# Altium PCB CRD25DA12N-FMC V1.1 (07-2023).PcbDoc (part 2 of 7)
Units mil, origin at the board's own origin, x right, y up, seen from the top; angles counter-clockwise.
Board outline 8000 x 8000 mil, 6 copper layers (Top Layer, Layer 2, Layer 3, Layer 4, Layer 5, Bottom Layer), stack 91 mil thick; 542 components, 315 nets, 1585 pads, 558 vias.
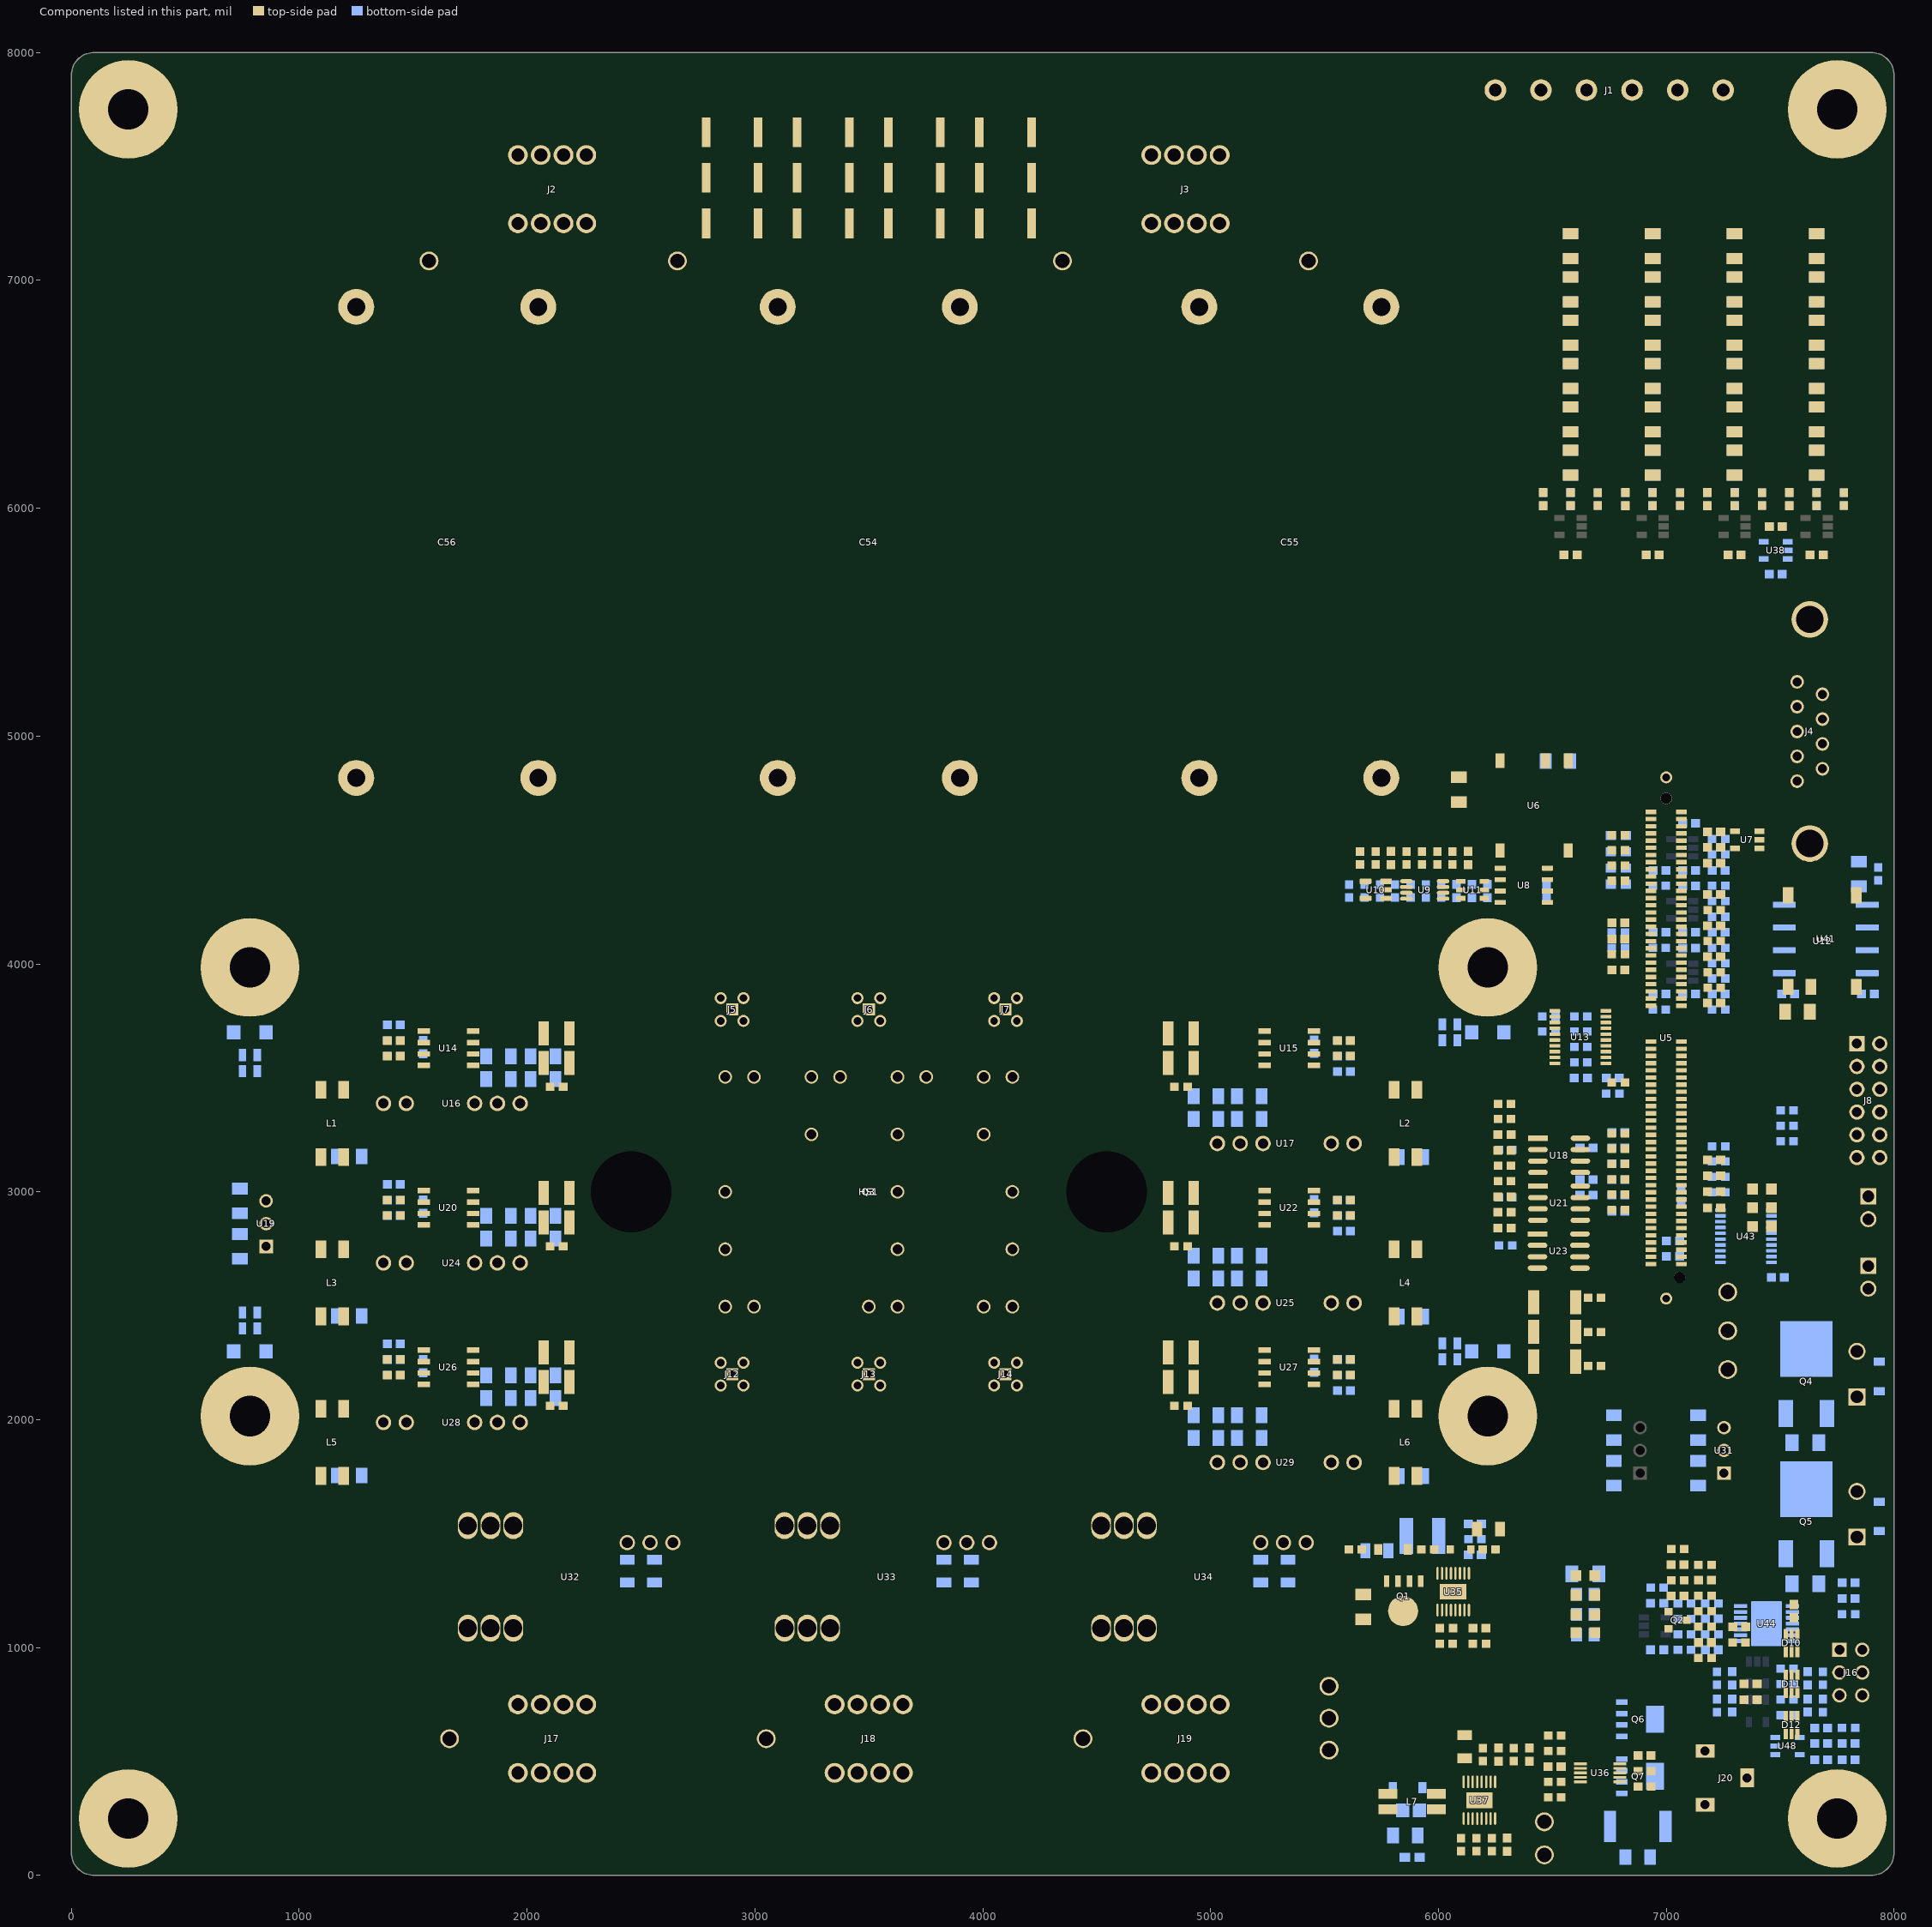
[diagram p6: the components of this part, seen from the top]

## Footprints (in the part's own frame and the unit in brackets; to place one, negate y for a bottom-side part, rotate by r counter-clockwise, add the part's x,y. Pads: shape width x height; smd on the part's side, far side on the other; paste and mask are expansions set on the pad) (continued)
CONV_R-78E5.0-1.0 [mm]
  rect 1.508x1.508 hole 1: 1(-2.54,-2.25)
  round 1.508 hole 1: 2(0,-2.25) 3(2.54,-2.25)
  silkscreen extent -6.5,-4.25 5.75,4.25, body extent -5.8,-4.25 5.8,4.25, height 9.9
CUI-PJ-102B_V [mm] "THD, 3-Leads, Body 14.4x9mm, Height 11mm"
  rect 1.5x2.1 hole 1 slot 1.6 at 90 deg: 1(-3,0) 2(3,0)
  rect 2.1x1.5 hole 1 slot 1.6 at 0 deg: 3(0,4.7)
  silkscreen extent -4.42,-4.5 10.7,4.9, body extent -3.7,-4.5 10.7,4.9, height 11
D0008B_HV [mm]
  rect 1.4x0.6 smd paste+0 mask+0: 1(-2.75,1.905) 2(-2.75,0.635) 3(-2.75,-0.635) 4(-2.75,-1.905) 5(2.75,-1.905) 6(2.75,-0.635) 7(2.75,0.635) 8(2.75,1.905)
  silkscreen extent -3.3,-2.5 0.9,3.35, body extent -3.01,-2.45 3.01,2.45, height 1.63
D0008B_L [mm] "SOIC, 8-Leads, Body 5x4mm, Pitch 1.27mm, IPC High Density"
  rrect18% 1.25x0.55 smd: 1(-2.625,1.905) 2(-2.625,0.635) 3(-2.625,-0.635) 4(-2.625,-1.905) 5(2.625,-1.905) 6(2.625,-0.635) 7(2.625,0.635) 8(2.625,1.905)
  silkscreen extent -2.75,-2.5 1.6,2.85, body extent -3,-2.45 3,2.45, height 1.63
DUB0008A_M [mm] "SOP, 8-Leads, Body 6.7x9.6mm, Pitch 2.54mm, IPC Low Density"
  rrect14% 2.55x0.7 smd: 1(-4.625,3.81) 2(-4.625,1.27) 3(-4.625,-1.27) 4(-4.625,-3.81) 5(4.625,-3.81) 6(4.625,-1.27) 7(4.625,1.27) 8(4.625,3.81)
  silkscreen extent -4.75,-4.8 2.95,4.83, body extent -5.24,-4.75 5.24,4.75, height 4.85
FM3_SIX-PACK_3PHASE_CRW [mm]
  round 1.524 hole 1.1: DC+_1(-6.4,-6.4) DC+_2(3.2,-6.4) DC+_3(12.8,-6.4) DC-1(-16,0) DC-2(3.2,0) DC-3(16,0) G1(-12.8,-12.8) G2(-16,12.8) G3(-3.2,-12.8) G4(3.2,12.8) G5(6.4,-12.8) G6(16,12.8) NTC1(12.8,-12.8) NTC2(16,-12.8) S1(-16,-12.8) S2(-12.8,12.8) S3(-6.4,-12.8) S4(0,12.8) S5(3.2,-12.8) S6(12.8,12.8) U(-16,6.4) V(3.2,6.4) W(16,6.4)
  round 0 hole 9 unplated: MH1(-26.5,0) MH2(26.5,0)
  Bottom Layer keep-out circle w0.254: c-16,-12.8 r5
  Bottom Layer keep-out circle w0.254: c-12.8,-12.8 r5
  Bottom Layer keep-out circle w0.254: c-6.4,-12.8 r5
  Bottom Layer keep-out circle w0.254: c-3.2,-12.8 r5
  Bottom Layer keep-out circle w0.254: c3.2,-12.8 r5
  Bottom Layer keep-out circle w0.254: c6.4,-12.8 r5
  Bottom Layer keep-out circle w0.254: c12.997,-12.859 r5
  Bottom Layer keep-out circle w0.254: c16,-12.8 r5
  Bottom Layer keep-out circle w0.254: c16,12.8 r5
  Bottom Layer keep-out circle w0.254: c12.8,12.8 r5
  Bottom Layer keep-out circle w0.254: c3.2,12.8 r5
  Bottom Layer keep-out circle w0.254: c0,12.8 r5
  Bottom Layer keep-out circle w0.254: c-12.8,12.8 r5
  Bottom Layer keep-out circle w0.254: c-16,12.8 r5
  silkscreen extent -31.52,-16.88 31.52,16.88, body extent -31.4,-16.9 31.4,16.9, height 11.98
FP-73415-1471-MFG [mm]
  rect 1.34x1.34 hole 0.84 paste-1000 mask+0: 1(0.01,0)
  round 1.34 hole 0.84 paste-1000 mask+0: 2(-1.27,1.27) 3(1.27,1.27) 4(-1.27,-1.27) 5(1.27,-1.27)
  silkscreen extent -2.54,-1.82 1.82,1.82, body extent -2.04,-2.04 2.04,2.04, height 0.25
FP-61301221121-MFG [mm]
  rect 1.7x1.7 hole 1.1 paste-1000 mask+0: 1(-6.35,-1.27)
  round 1.7 hole 1.1 paste-1000 mask+0: 2(-6.35,1.27) 3(-3.81,-1.27) 4(-3.81,1.27) 5(-1.27,-1.27) 6(-1.27,1.27) 7(1.27,-1.27) 8(1.27,1.27) 9(3.81,-1.27) 10(3.81,1.27) 11(6.35,-1.27) 12(6.35,1.27)
  silkscreen extent -8.38,-2.62 7.77,2.62, body extent -7.87,-2.72 7.87,2.72, height 0.25
FP-APTR3216SECK-MFG [mm]
  rect 1.5x1.6 smd paste+0 mask+0: 1(-1.8,0) 2(1.8,0)
  silkscreen extent -3.3,-1.4 1.9,1.4, body extent -1.6,-0.8 1.6,0.8, height 1.1
FP-C0603C-CF-IPC_B [mil]
  rect 39.63x37.73 smd paste+0 mask+0: 1(-28.58,0) 2(28.58,0)
  silkscreen extent -48,-35 48,35, body extent -31,-16 31,16, height 34
FP-CL21-IPC_A [mil]
  rect 57.27x61.27 smd paste+0 mask+0: 1(-36.45,0) 2(36.45,0)
  silkscreen extent -65,-46 65,46, body extent -39,-25 39,25, height 57
FP-CL31-IPC_B [mil]
  rect 51.4x69.22 smd paste+0 mask+0: 1(-54.19,0) 2(54.19,0)
  silkscreen extent -17,-35 17,35, body extent -63,-31 63,31, height 55
FP-CL31-IPC_C [mil]
  rect 43.52x65.28 smd paste+0 mask+0: 1(-50.25,0) 2(50.25,0)
  silkscreen extent -17,-34 17,34, body extent -76,-38 76,38, height 10
FP-CRGCQ0603-IPC_A [mil]
  rect 45.6x39.85 smd paste+0 mask+0: 1(-32.56,0) 2(32.56,0)
  silkscreen extent -55,-36 55,36, body extent -31,-16 31,16, height 22
FP-CRGP2512-IPC_C [mil]
  rect 37.72x130.17 smd paste+0 mask+0: 1(-114.25,0) 2(114.25,0)
  silkscreen extent -84,-67 84,67, body extent -125,-63 125,63, height 26
FP-D0008A-IPC_B [mil]
  rect 85.4x22.92 smd paste+0 mask+0: 1(-93.06,75)
  rrect100% 85.4x22.92 smd paste+0 mask+0: 2(-93.06,25) 3(-93.06,-25) 4(-93.06,-75) 5(93.06,-75) 6(93.06,-25) 7(93.06,25) 8(93.06,75)
  silkscreen extent -162,-97 31,97, body extent -146,-106 146,106, height 10
FP-DDC0005A-MFG [mm]
  rect 1.1x0.6 smd paste+0 mask+0: 1(-1.35,0.95) 2(-1.35,0) 3(-1.35,-0.95) 4(1.35,-0.95) 5(1.35,0.95)
  silkscreen extent -2.6,-1.53 0.87,1.53, body extent -2,-1.63 2,1.63, height 0.25
FP-GCM188-0_1-IPC_A [mil]
  rect 45.62x39.85 smd paste+0 mask+0: 1(-32.55,0) 2(32.55,0)
  silkscreen extent -55,-36 55,36, body extent -31,-16 31,16, height 35
FP-LTST-C171GKT-MFG [mm]
  rect 1.2x1.2 smd paste+0 mask+0: 1(-1.05,0) 2(1.05,0)
  silkscreen extent -2.37,-1.05 1.05,1.05, body extent -1.75,-0.77 1.75,0.77, height 0.25
FP-LTST-C171GKT-MFG-RED [mm]
  rect 1.2x1.2 smd paste+0 mask+0: 1(-1.05,0) 2(1.05,0)
  silkscreen extent -2.37,-1.05 1.05,1.05, body extent -1,-0.63 1,0.63, height 0.8
FP-LTST-C171GKT-MFG-YELLOW [mm]
  rect 1.2x1.2 smd paste+0 mask+0: 1(-1.05,0) 2(1.05,0)
  silkscreen extent -2.37,-1.05 1.05,1.05, body extent -1,-0.63 1,0.63, height 0.8
FP-MCR03-IPC_B [mil]
  rect 37.72x35.91 smd paste+0 mask+0: 1(-28.62,0) 2(28.62,0)
  silkscreen extent -47,-34 47,34, body extent -31,-16 31,16, height 22
FP-MCR10-IPC_A [mil]
  rect 49.53x57.56 smd paste+0 mask+0: 1(-38.46,0) 2(38.46,0)
  silkscreen extent -63,-45 63,45, body extent -39,-25 39,25, height 26
FP-MCR18-IPC_A [mil]
  rect 57.31x73.16 smd paste+0 mask+0: 1(-59.1,0) 2(59.1,0)
  silkscreen extent -19,-37 19,37, body extent -63,-31 63,31, height 26
FP-NR5040-H_4_1-MFG [mm]
  rect 1.5x4 smd paste+0 mask+0: 1(-1.8,0) 2(1.8,0)
  silkscreen extent -2.55,-2.55 2.55,2.55, body extent -2.45,-2.45 2.45,2.45, height 4.1
FP-PowerDI5060-8-MFG [mm]
  rect 0.61x1.27 smd paste+0 mask+0: 1(-1.905,-2.67) 2(-0.635,-2.67) 3(0.635,-2.67) 4(1.905,-2.67)
  rect 3x2 smd paste+0 mask+0: 5(0,1.05)
  Top Layer region: 2.05,-1.215 -2.05,-1.215 -2.05,-1.035 -2.805,-1.035 -2.805,-0.435 -2.05,-0.435 -2.05,1.39 -2.805,1.39 -2.805,1.99 -2.05,1.99 -2.05,2.285 -2.21,2.285 -2.21,3.305 -1.6,3.305 -1.6,2.595 -0.94,2.595 -0.94,3.305 -0.33,3.305 -0.33,2.595 0.33,2.595 0.33,3.305 0.94,3.305 0.94,2.595 1.6,2.595 1.6,3.305 2.21,3.305 2.21,2.285 2.05,2.285 2.05,1.99 2.805,1.99 2.805,1.39 2.05,1.39 2.05,-0.435 2.805,-0.435 2.805,-1.035 2.05,-1.035
  silkscreen extent -3.2,-2.73 2.55,-1.59, body extent -2.58,-3.08 2.58,3.08, height 1.15
FP-PWP0014H-MFG [mm]
  rrect22% 1.5x0.45 smd paste+0 mask+0: 1(-2.9,1.95) 2(-2.9,1.3) 3(-2.9,0.65) 4(-2.9,0) 5(-2.9,-0.65) 6(-2.9,-1.3) 7(-2.9,-1.95) 8(2.9,-1.95) 9(2.9,-1.3) 10(2.9,-0.65) 11(2.9,0) 12(2.9,0.65) 13(2.9,1.3) 14(2.9,1.95)
  rrect3% 3.4x5 smd paste-1000 mask-1000: 15(0,0)
  silkscreen extent -4.35,-2.6 2.25,2.6, body extent -3.2,-2.5 3.2,2.5, height 1.2
FP-R1SE-0505-R-MFG [mm]
  rect 1.8x1.2 smd paste+0 mask+0: 1(-5.1,3.81) 2(-5.1,1.27) 4(-5.1,-3.81) 5(5.1,-3.81) 8(5.1,3.81)
  silkscreen extent -6.77,-6.5 5.35,6.5, body extent -6.1,-6.6 6.1,6.6, height 0.25
FP-RL2512-IPC_A [mil]
  rect 53.47x136.15 smd paste+0 mask+0: 1(-122.13,0) 2(122.13,0)
  silkscreen extent -84,-68 84,68, body extent -123,-63 127,63, height 26
FP-S17-0173-SINGLE-MFG [mm]
  rect 1.27x0.61 smd paste+0 mask+0: 1(-2.67,1.905) 2(-2.67,0.635) 3(-2.67,-0.635) 4(-2.67,-1.905)
  round 3.356 smd paste+0 mask+0: 5-6-7-8(0.65,-0.069)
  Top Layer region: -1.215,1.955 2.285,1.955 2.285,2.21 3.305,2.21 3.305,1.6 2.595,1.6 2.595,0.94 3.305,0.94 3.305,0.33 2.595,0.33 2.595,-0.33 3.305,-0.33 3.305,-0.94 2.595,-0.94 2.595,-1.6 3.305,-1.6 3.305,-2.21 2.285,-2.21 2.285,-1.955 -1.215,-1.955
  silkscreen extent -4.02,-2.59 3,2.59, body extent -3.4,-2.73 3.4,2.73, height 0.25
FP-USC-MFG [mm]
  rect 0.8x0.9 smd paste+0 mask+0: 1(-1.15,0) 2(1.15,0)
  silkscreen extent -2.22,-0.72 0.38,0.72, body extent -1.65,-0.82 1.65,0.82, height 0.25
KSTN-5010_V [mm] "Test Point, Dia 3.17mm"
  round 2.1 hole 1.6: 1(0,0)
  silkscreen extent -1.59,-1.58 1.59,1.58, body extent -1.59,-1.59 1.59,1.59, height 8.13
KSTN-5011_V [mm] "Test Point, Dia 3.17mm"
  round 2.1 hole 1.6: 1(0,0)
  silkscreen extent -1.59,-1.58 1.59,1.58, body extent -1.59,-1.59 1.59,1.59, height 8.13
KSTN-5012_V [mm] "Test Point, Dia 3.17mm"
  round 2.1 hole 1.6: 1(0,0)
  silkscreen extent -1.59,-1.58 1.59,1.58, body extent -1.59,-1.59 1.59,1.59, height 8.13
L717SDE09PA4CH4RC309 [mm] "CONN D-SUB PLUG 9POS R/A SLDR"
  round 1.508 hole 1: 1(-5.54,1.42) 2(-2.77,1.42) 3(0,1.42) 4(2.77,1.42) 5(5.54,1.42) 6(-4.155,-1.42) 7(-1.385,-1.42) 8(1.385,-1.42) 9(4.155,-1.42)
  round 4.066 hole 3.05: 10(-12.495,0) 11(12.495,0)
  silkscreen extent -15.7,-8.5 15.7,3.4, body extent -15.4,-15.6 15.41,3, height 12.55
"LA 6 150 12" [mm]
  round 11 hole 4.5: 1(-69,25) 2(69,25) 3(-69,-25) 4(69,-25)
  body extent -104.53,-31.05 74.97,30.95, height 86.05
"LAH 50-P" [mil]
  oval 118.74x86.61 hole 78.74 mask+7.87: 1(235,370) 2(235,270) 3(235,170) 5(-215,270) 6(-215,170)
  oval 118.74x86.61 hole 78.74 paste+0 mask+7.87: 4(-215,370)
  round 67.24 hole 47.24: 7(160,-330) 8(160,-430) 9(160,-530)
  silkscreen extent -285,-635 305,675, body extent -284,-636 304,675, height 790
LT-MSE-16-EDP_L [mm] "SOP, 16-Leads, Body 4.1x3.1mm, Pitch 0.5mm, Thermal Pad 2.95x1.76mm, IPC High Density"
  oval 1.4x0.25 smd: 1(-2.05,1.75) 2(-2.05,1.25) 3(-2.05,0.75) 4(-2.05,0.25) 5(-2.05,-0.25) 6(-2.05,-0.75) 7(-2.05,-1.25) 8(-2.05,-1.75) 9(2.05,-1.75) 10(2.05,-1.25) 11(2.05,-0.75) 12(2.05,-0.25) 13(2.05,0.25) 14(2.05,0.75) 15(2.05,1.25) 16(2.05,1.75)
  rect 1.76x2.95 smd: 17(0,0)
  silkscreen extent -2.17,-2.08 0.95,2.55, body extent -1.55,-2.05 1.55,2.05, height 1.1
MGJ2D121509SC [mm]
  round 1.725 hole 1.15: 1(-7.62,2.23) 2(-5.08,2.23) 5(2.54,2.23) 6(5.08,2.23) 7(7.62,2.23)
  silkscreen extent -10.52,-4.9 9.75,4.9, body extent -9.9,-5.09 9.6,4.73, height 13.09
MH_M4_P [mm] "M4 plated mounting hole"
  round 11 hole 4.5: 1(0,0)
  body extent -4,-4.62 4,4.62, height 102.05
MSD7342682MLC [mm]
  rect 1.1x2.1 smd: 1(0.85,2.7) 2(-0.85,2.7) 3(-0.85,-2.7) 4(0.85,-2.7)
  silkscreen extent -3.75,-3.75 3.75,4.25, body extent -3.75,-3.75 3.75,3.75, height 4.7
MSOP-MS8_L [mm] "TSOP, 8-Leads, Body 3x3mm, Pitch 0.65mm, IPC High Density"
  oval 1.4x0.45 smd: 1(-2.05,0.975) 2(-2.05,0.325) 3(-2.05,-0.325) 4(-2.05,-0.975) 5(2.05,-0.975) 6(2.05,-0.325) 7(2.05,0.325) 8(2.05,0.975)
  silkscreen extent -2.17,-1.55 0.95,1.87, body extent -1.55,-1.55 1.55,1.55, height 1.1
ONSC-DPAK-3-369C-01_V [mm] "DPAK, 3-Leads, Body 6.54x6.095mm, Pitch 2.29mm"
  rect 3x1.6 smd: 1(-4.4,2.29) 3(-4.4,-2.29)
  rect 6.2x5.8 smd: 4(2.8,0)
  silkscreen extent -4.52,-3.27 -0.45,3.77, body extent -1.6,-3.27 4.49,3.27, height 2.38
ONSC-SOD-123FL-2-498-01_V [mm] "SOD, 2-Leads, Body 2.7x1.65mm"
  rect 0.91x1.22 smd: 1(-1.635,0) 2(1.635,0)
  silkscreen extent -1.76,-0.82 0.78,1.28, body extent -1.35,-0.82 1.35,0.82, height 1
ONSC-SOT-23-3-318-08_V [mm] "SOT23, 3-Leads, Body 2.92x1.3mm, Pitch 0.95mm"
  rect 0.9x0.8 smd: 1(-1,0.95) 2(-1,-0.95) 3(1,0)
  silkscreen extent -1.12,-1.46 0.65,2.02, body extent -0.65,-1.46 0.65,1.46, height 1.11
PW0020A_L [mm] "SOP, 20-Leads, Body 6.6x4.5mm, Pitch 0.65mm, IPC High Density"
  rrect25% 1.2x0.4 smd: 1(-2.85,2.925) 2(-2.85,2.275) 3(-2.85,1.625) 4(-2.85,0.975) 5(-2.85,0.325) 6(-2.85,-0.325) 7(-2.85,-0.975) 8(-2.85,-1.625) 9(-2.85,-2.275) 10(-2.85,-2.925) 11(2.85,-2.925) 12(2.85,-2.275) 13(2.85,-1.625) 14(2.85,-0.975) 15(2.85,-0.325) 16(2.85,0.325) 17(2.85,0.975) 18(2.85,1.625) 19(2.85,2.275) 20(2.85,2.925)
  silkscreen extent -2.98,-3.3 1.85,3.8, body extent -3.21,-3.25 3.21,3.25, height 1
RESC2010(5025)_N [mm] "Chip Resistor, Body 5.0x2.5mm, IPC Medium Density"
  rect 1.25x2.7 smd: 1(-2.35,0) 2(2.35,0)
  silkscreen extent -1.35,-1.25 1.35,1.25, body extent -2.6,-1.35 2.6,1.35, height 0.71
RESC2013X50X30LL20T20 [mm] "Chip Resistor, 2-Leads, Body 2.00x1.25mm, IPC High Density"
  rect 0.85x1.35 smd: 1(-0.825,0) 2(0.825,0)
  silkscreen extent -0.1,-0.58 0.1,0.58, body extent -1.1,-0.72 1.1,0.72, height 0.5
RESC3125X70X40NL20T20 [mm] "Chip Resistor, 2-Leads, Body 3.10x2.50mm, IPC Medium Density"
  rect 1.15x2.7 smd: 1(-1.425,0) 2(1.425,0)
  silkscreen extent -0.45,-1.25 0.45,1.25, body extent -1.65,-1.35 1.65,1.35, height 0.7
RESC3216X65X50NL15T25 [mm] "Chip Resistor, 2-Leads, Body 3.20x1.60mm, IPC Medium Density"
  rect 1.25x1.75 smd: 1(-1.4,0) 2(1.4,0)
  silkscreen extent -0.4,-0.77 0.4,0.77, body extent -1.68,-0.87 1.68,0.87, height 0.65
SOP50P490X110-10N [mm]
  rect 1.425x0.3 smd: 1(-2.212,1) 2(-2.212,0.5) 3(-2.212,0) 4(-2.212,-0.5) 5(-2.212,-1) 6(2.212,-1) 7(2.212,-0.5) 8(2.212,0) 9(2.212,0.5) 10(2.212,1)
  silkscreen extent -2.92,-1.5 1.15,1.5, body extent -2.45,-1.5 2.45,1.5, height 1.1
SOT65P222X120-6N [mm]
  rect 1.15x0.45 smd: 1(-1,0.65) 2(-1,0) 3(-1,-0.65) 4(1,-0.65) 5(1,0) 6(1,0.65)
  silkscreen extent -1.58,-1 0.08,1.22, body extent -1.11,-1 1.11,1, height 1.2
SOT95P280X100-6N [mm]
  rect 1.05x0.55 smd: 1(-1.3,0.95) 2(-1.3,0) 3(-1.3,-0.95) 4(1.3,-0.95) 5(1.3,0) 6(1.3,0.95)
  silkscreen extent -1.83,-1.45 0.43,1.58, body extent -1.4,-1.45 1.4,1.45, height 1
SOT95P280X145-5N [mm]
  rrect25% 1.32x0.59 smd: 1(-1.145,0.95) 2(-1.145,0) 3(-1.145,-0.95) 4(1.145,-0.95) 5(1.145,0.95)
  silkscreen extent -2.51,-1.57 0.8,1.57, body extent -1.25,-1.5 1.25,1.5, height 1.11
TECO-640456-2_V [mm] "HDR, 2-Leads, Body 5.715x5.08mm, Pitch 2.54mm"
  rect 1.8x1.8 hole 1.3: 1(1.27,0)
  round 1.8 hole 1.3: 2(-1.27,0)
  silkscreen extent -2.54,-2.54 3.26,3.17, body extent -2.54,-2.67 2.54,3.17, height 10.09
TMDSCNCD280039C [mm]
  rect 0.5x1.2 smd paste+0 mask+0: 1(25.2,1.7) 2(25.2,-1.7) 3(24.4,1.7) 4(24.4,-1.7) 5(23.6,1.7) 6(23.6,-1.7) 7(22.8,1.7) 8(22.8,-1.7) 9(22,1.7) 10(22,-1.7) 11(21.2,1.7) 12(21.2,-1.7) 13(20.4,1.7) 14(20.4,-1.7) 15(19.6,1.7) 16(19.6,-1.7) 17(18.8,1.7) 18(18.8,-1.7) 19(18,1.7) 20(18,-1.7) 21(17.2,1.7) 22(17.2,-1.7) 23(16.4,1.7) 24(16.4,-1.7) 25(15.6,1.7) 26(15.6,-1.7) 27(14.8,1.7) 28(14.8,-1.7) 29(14,1.7) 30(14,-1.7) 31(13.2,1.7) 32(13.2,-1.7) 33(12.4,1.7) 34(12.4,-1.7) 35(11.6,1.7) 36(11.6,-1.7) 37(10.8,1.7) 38(10.8,-1.7) 39(10,1.7) 40(10,-1.7) 41(9.2,1.7) 42(9.2,-1.7) 43(8.4,1.7) 44(8.4,-1.7) 45(7.6,1.7) 46(7.6,-1.7) 47(6.8,1.7) 48(6.8,-1.7) 49(6,1.7) 50(6,-1.7) 51(5.2,1.7) 52(5.2,-1.7) 53(4.4,1.7) 54(4.4,-1.7) 55(3.6,1.7) 56(3.6,-1.7) 57(-0.4,1.7) 58(-0.4,-1.7) 59(-1.2,1.7) 60(-1.2,-1.7) 61(-2,1.7) 62(-2,-1.7) 63(-2.8,1.7) 64(-2.8,-1.7) 65(-3.6,1.7) 66(-3.6,-1.7) 67(-4.4,1.7) 68(-4.4,-1.7) 69(-5.2,1.7) 70(-5.2,-1.7) 71(-6,1.7) 72(-6,-1.7) 73(-6.8,1.7) 74(-6.8,-1.7) 75(-7.6,1.7) 76(-7.6,-1.7) 77(-8.4,1.7) 78(-8.4,-1.7) 79(-9.2,1.7) 80(-9.2,-1.7) 81(-10,1.7) 82(-10,-1.7) 83(-10.8,1.7) 84(-10.8,-1.7) 85(-11.6,1.7) 86(-11.6,-1.7) 87(-12.4,1.7) 88(-12.4,-1.7) 89(-13.2,1.7) 90(-13.2,-1.7) 91(-14,1.7) 92(-14,-1.7) 93(-14.8,1.7) 94(-14.8,-1.7) 95(-15.6,1.7) 96(-15.6,-1.7) 97(-16.4,1.7) 98(-16.4,-1.7) 99(-17.2,1.7) 100(-17.2,-1.7) 101(-18,1.7) 102(-18,-1.7) 103(-18.8,1.7) 104(-18.8,-1.7) 105(-19.6,1.7) 106(-19.6,-1.7) 107(-20.4,1.7) 108(-20.4,-1.7) 109(-21.2,1.7) 110(-21.2,-1.7) 111(-22,1.7) 112(-22,-1.7) 113(-22.8,1.7) 114(-22.8,-1.7) 115(-23.6,1.7) 116(-23.6,-1.7) 117(-24.4,1.7) 118(-24.4,-1.7) 119(-25.2,1.7) 120(-25.2,-1.7)
  round 1.34 hole 0.84 paste-1000 mask+0: 121(-29.05,0) 122(29.05,0)
  round 1.27 hole 1.27 unplated paste-1000 mask+0: ""(-26.7,-1.5) ""(26.7,0)
  silkscreen extent -33.55,-4.25 33.55,3.56, body extent -33.87,-4.89 34.67,5.68, height 57.35
TRACO-TES1-5_V [mm] "SMD, 5-Leads, Body 13.7x8.0mm"
  rect 1.6x1 smd paste+0: 1(-5,3.81) 2(-5,1.27) 4(-5,-3.81) 5(5,-3.81) 8(5,3.81)
  silkscreen extent -5.12,-6.85 3.8,6.85, body extent -5.5,-6.95 5.5,6.95, height 7.15
WE-SL2 [mm] "SMD Inductor, 4-Leads, Body 6.3 x 9.5 mm"
  rect 2x1.2 smd: 1(-3.75,1.27) 2(-3.75,-1.27) 3(3.75,-1.27) 4(3.75,1.27)
  silkscreen extent -4.7,-3.18 4.7,3.18, body extent -4.6,-3 4.6,3, height 5

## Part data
C1 C17 C19 C21 C28 C34 C35 C51 C60 C69 C78 C84 C169: "CAP CER 4700PF 25V 10% X7R 0603", Capacitance=4.7nF, Case Code (Imperial)=0603, Case Code (Metric)=1608, Dielectric=X7R, Dielectric Material=Ceramic, Manufacturer=KEMET, Manufacturer Part Number=C0603C472K3RACTU, Max Operating Temperature=125°C, Min Operating Temperature=-55°C, Package Quantity=1, Supplier Part Number 1=67AH9250, TOLERANCE=10%, Voltage Rating=25V
C2 C3 C4 C39 C45 C57 C58 C59: "CAP CER 10000PF 25V X7R 0603", Capacitance=10nF, Case Code (Imperial)=0603, Case Code (Metric)=1608, Manufacturer=SAMSUNG, Max Operating Temperature=125°C, Min Operating Temperature=-55°C, Ratings=AEC-Q200, TOLERANCE=10%, Voltage Rating=25V
C5 C6 C7 C8 C9 C11 C12 C13 C14 C15 C27 C32 C38 C42 C44 C46 C47 C53 C61 C62 C64 C73 C74 C75 C76 C77 C81 C82 C83 C104 C109 C111 C114 C126 C129 C167 C171 C172 C177 C179 C180 C181: library part CMP-2006-03057-2, "CAP CER 0.1UF 25V X7R 0603", Capacitance=0.10μF, Manufacturer=KEMET, Package=0603, Temperature="-55°C to +125°C", Temperature Characteristic=X7R, Temperature Coefficient=30ppm/°C, Temperature Range High=+125°C, Temperature Range Low=-55°C, TOLERANCE=0.1, Voltage Rating=25V
C10 C23 C40 C63 C67 C91 C92 C96 C97 C98 C99 C100 C101 C105 C106 C112 C122 C123 C125 C127 C128 C130 C131 C133 C134 C135 C136 C143 C144 C146 C147 C148 C149 C150 C151 C152 C153 C154 C155 C156 C157 C183 C184: library part CMP-13271-001434-1, "CAP CER 10UF 25V X7R 1206", Capacitance=10μF, Case Code (Imperial)=1206, Case Code (Metric)=3216, Dielectric=X7R, Manufacturer=SAMSUNG, Max Operating Temperature=125°C, Min Operating Temperature=-55°C, Package Quantity=1, TOLERANCE=10%, Voltage Rating=25V
C16 C18 C41 C50 C158: library part CMP-2006-03716-2, "CAP CER 1000PF 50V X7R 0603", Capacitance=1nF, Manufacturer=KEMET, Package=0603, Temperature="-55°C to +125°C", Temperature Characteristic=X7R, Temperature Coefficient=30ppm/°C, Temperature Range High=+125°C, Temperature Range Low=-55°C, TOLERANCE=0.1, Voltage Rating="50 V"
C20 C22 C24 C25 C26 C29 C30 C31 C33 C36 C49 C90 C94 C102 C103 C107 C108 C113 C115 C116 C119 C120 C121 C138 C139 C142 C160: "CAP CER 56PF 50V C0G/NP0 0603", Capacitance=56pF, Case Code (Imperial)=0603, Case Code (Metric)=1608, Dielectric=C0G, Manufacturer=SAMSUNG, Max Operating Temperature=125°C, Min Operating Temperature=-55°C, Package Quantity=1, Temperature Coefficient=30ppm/°C, TOLERANCE=5%, Voltage=50V
C37 C48 C159 C161 C162 C163 C164 C165 C166: library part CMP-13271-001123-1, "CAP CER 4.7UF 50V X7R 1206", Capacitance=4.7μF, Case Code (Imperial)=1206, Case Code (Metric)=3216, Dielectric=X7R, Manufacturer=SAMSUNG, Max Operating Temperature=125°C, Min Operating Temperature=-55°C, Package Quantity=1, TOLERANCE=10%, Voltage Rating=50V
C43 C170: "CAP CER 18PF 50V C0G/NP0 0603", Capacitance=18pF, Case Code (Imperial)=0603, Case Code (Metric)=1608, Dielectric=C0G, Dielectric Material=Ceramic, Insulation Resistance=100GR, Manufacturer="KYOCERA AVX", Max Operating Temperature=125°C, Min Operating Temperature=-55°C, Package Quantity=1, Supplier Part Number 1=1349617, Temperature Coefficient=30ppm/°C, TOLERANCE=5%, Voltage=50V
C52: "CAP CER 0.022UF 50V X7R 0805", Capacitance=22nF, Case Code (Imperial)=0805, Case Code (Metric)=2012, Dielectric=X7R, Dielectric Material=Ceramic, Insulation Resistance=100GR, Manufacturer=YAGEO, Max Operating Temperature=125°C, Min Operating Temperature=-55°C, Package Quantity=1, Supplier Part Number 1=2104784, TOLERANCE=10%, Voltage=50V
C54 C55 C56: "CAP FILM 65UF 5% 1.1KVDC RAD", Capacitance=65µF, Manufacturer=KEMET, Package=RADIAL, Supplier Part Number 1=399-C4AQQEW5650A3BJ-ND, Voltage=1.1kV
C65 C66 C68 C72: library part CMP-06035-043171-1, "CAP CER 0.27UF 16V X7R 0603", Capacitance=0.27μF, Dielectric=X7R, Manufacturer=MURATA, Package=0603, TOLERANCE=10%, Voltage Rating (DC)=16V
C70 C71 C79 C80 C85 C86: "CAP CER 100PF 50V C0G/NP0 0603", Capacitance=100pF, Case Code (Imperial)=0603, Case Code (Metric)=1608, Dielectric=C0G, Manufacturer=SAMSUNG, Max Operating Temperature=125°C, Min Operating Temperature=-55°C, Package Quantity=1, Supplier Part Number 1=7665130, Temperature Coefficient=300ppm/°C, TOLERANCE=5%, Voltage=50V
C87 C88 C89 C93 C95 C110 C117 C118 C124 C132 C137 C140 C141 C145: "CAP CER 2.2UF 50V X5R 0603", Capacitance=2.2μF, Case Code (Imperial)=0603, Case Code (Metric)=1608, Manufacturer=MURATA, Max Operating Temperature=85°C, Min Operating Temperature=-55°C, Ratings=AEC-Q200, TOLERANCE=20%, Voltage Rating=50V
C168 C174 C176 C178: library part CMP-03020-020944-2, "CAP CER 330PF 250V C0G/NP0 0603", Capacitance=330pF, Manufacturer=KEMET, Package=0603, Temperature="-55°C to +125°C", Temperature Characteristic=C0G, Temperature Coefficient=30ppm/°C, Temperature Range High=+125°C, Temperature Range Low=-55°C, TOLERANCE=0.05, Voltage Rating="250 V"
C173 C175: "CAP CER 47PF 100V C0G/NP0 0603", Capacitance=47pF, Case Code (Imperial)=0603, Case Code (Metric)=1608, Dielectric=C0G, Dielectric Material=Ceramic, Manufacturer=KEMET, Max Operating Temperature=125°C, Min Operating Temperature=-55°C, Package Quantity=4000, Supplier Part Number 1=8015369, Temperature Coefficient=30ppm/°C, TOLERANCE=5%, Voltage=100V
C182: "CAP CER 1UF 50V X7R 0805", Capacitance=1μF, Case Code (Imperial)=0805, Case Code (Metric)=2012, Dielectric=X7R, Manufacturer=SAMSUNG, Max Operating Temperature=125°C, Min Operating Temperature=-55°C, Package Quantity=1, Supplier Part Number 1=82AC9436, TOLERANCE=10%, Voltage=50V
D1: "LED RED DIFFUSED 0805 SMD", Case Code (Imperial)=0805, Case Code (Metric)=2012, Color=RED, Forward Current=20mA, Forward Voltage=2V, Illumination Color=Red, Manufacturer="VISUAL COMMUNICATIONS", Max Operating Temperature=85°C, Min Operating Temperature=-40°C, Package Quantity=1, Power Rating=100mW, Reverse Voltage=5V, Supplier Part Number 1=45X6246
D2: "LED YELLOW CLEAR 0805 SMD", Case Code (Imperial)=0805, Case Code (Metric)=2012, Color=Yellow, Forward Current=30mA, Forward Voltage=2V, Lens Color=Colorless, Manufacturer=LITE-ON, Max Operating Temperature=85°C, Max Power Dissipation=75mW, Min Operating Temperature=-55°C, Package Quantity=1, Reverse Voltage=5V, Supplier Part Number 1=6920950, Test Current=20mA
D3 D6 D7 D8 D9: library part CMP-22017-000007-1, "LED GREEN CLEAR CHIP SMD", Case Code (Imperial)=0805, Case Code (Metric)=2012, Color=GREEN, Forward Current=30mA, Forward Voltage=2.1V, Illumination Color=Green, Lens Color=Colorless, Manufacturer=LITE-ON, Max Operating Temperature=85°C, Min Operating Temperature=-55°C, Package Quantity=1, Power Dissipation=100mW, Reverse Voltage=5V, Test Current=10mA
D4 D17 D18 D19: "DIODE SCHOTTKY 60V 2A SOD123FL", Average Rectified Current=2A, Forward Voltage=700mV, Manufacturer="MICRO COMMERCIAL", Manufacturer Print=MICRO, Max Operating Temperature=125°C, Max Power Dissipation=1.68W, Max Repetitive Reverse Voltage (Vrrm)=60V, Max Reverse Current=500uA, Max Surge Current=50A, Min Operating Temperature=-65°C, Package=SOD-123F, Package Quantity=1, Supplier Part Number 1=SMD26PL-TPMSCT-ND
D5: "DIODE SCHOTTKY 30V 200MA USC", Average Rectified Current=200mA, Manufacturer=TOSHIBA, Max Operating Temperature=100°C, Max Repetitive Reverse Voltage (Vrrm)=30V, Max Reverse Current=5uA, Min Operating Temperature=-40°C, Package=SOD-323, Peak Non-Repetitive Surge Current=1A, Supplier Part Number 1=CUS520H3FCT-ND
D10 D11 D12: "DIODE ARRAY SCHOTTKY 40V SOT363", Manufacturer="MICRO COMMERCIAL", Manufacturer Print=MICRO, Manufacturer_Name="Micro Commercial Components (MCC)", Package=SOT-363
D13 D14 D15 D16: "LED PURPLE CLEAR 1206 SMD", Color=PURPLE, Manufacturer=Kingbright, Manufacturer Print=KINGBRIGHT, Package=1206, Supplier Part Number 1=604-APTR3216-VFX
HS1: "HEATSINK EXTRUSION 150MM", Manufacturer="FISCHER ELEKTRONIK", Manufacturer Part Number=LA6/15012V, Natural Thermal Resistance=0.175°C/W, Package=N/A, Power Consumption=2.9W, Supplier Part Number 1=42M1958
J1: "TERM BLOCK HDR 6POS VERT 5.08MM", Color=Green,Grey, Current=12A, Flammability Rating="UL94 V-0", Housing Color=Green, Manufacturer="PHOENIX CONTACT", Package=N/A, Package Quantity=50, Supplier Part Number 1=1896240, Voltage=300V, Voltage Rating=250V
J2 J3 J17 J18 J19: "TERM REDCUBE M4 8PIN PCB", Current Rating=80A, Manufacturer="WURTH ELEKTRONIK", Manufacturer Print=WURTH, Max Operating Temperature=135°C, Min Operating Temperature=-40°C, Package=N/A, Package Quantity=250, Supplier Part Number 1=1224952
J4: "CONN D-SUB PLUG 9POS R/A SLDR", Color=Black, Current Rating=5A, Manufacturer=AMPHENOL, Max Operating Temperature=155°C, Max Supply Voltage (AC)=250V, Min Operating Temperature=-55°C, Package=N/A, Supplier Part Number 1=70145033
J5 J6 J7 J12 J13 J14: "CONN MMCX JACK STR 50 OHM PCB", Manufacturer=MOLEX, Manufacturer Part Number=73415-1471, Max Frequency=6GHz, Operating Frequency=N/A, Package Quantity=500, Supplier Part Number 1=70364031
J8: "CONN HEADER VERT 12POS 2.54MM", Color=Black, Flammability Rating="UL94 V-0", Manufacturer="WURTH ELEKTRONIK", Manufacturer Print=WURTH, Max Operating Temperature=105°C, Min Operating Temperature=-40°C, Package=N/A, Supplier Part Number 1=732-5297-ND, Voltage Rating=250V
J9 J10: library part CMP-2000-05417-1, "CONN HEADER VERT 2POS 2.54MM", Color=White, Current, Rating="5 /  / A", Flammability Rating=UL94V-0, Manufacturer=TE, Package=N/A, Temperature, Operating="-55to+105 /  / degC", Voltage, Rating="250 /  / V"
J11 J15: "TERM BLOCK HDR 2POS VERT 5.08MM", Colour=Green, Manufacturer="PHOENIX CONTACT", Package=N/A, Supplier Part Number 1=1896199
J16: library part CMP-1502-00000-1, "CONN HEADER VERT 6POS 2.54MM", Contact Resistance=20mOhm, Manufacturer="WURTH ELECTRONIK", Operating Temperature=-40to125degC, Package=N/A, Withstanding Voltage=500VAC, Working Voltage=250VAC
J20: "CONN PWR JACK 2X5.5MM SOLDER", Color=Black, Current Rating=5A, Flammability Rating="UL94 V-0", Insulation Resistance=50MR, Manufacturer="CUI DEVICES", Max Operating Temperature=85°C, Min Operating Temperature=-25°C, Package=N/A, Package Quantity=280, Voltage Rating=24V
L1 L2 L3 L4 L5 L6: "CMC 10UH 1.6A 2LN 920 OHM SMD", Case/Package=SMD/SMT, Current=1.6A, DC Resistance (DCR)=80mR, Inductance=10uH, Manufacturer="WURTH ELECTRONIK", Manufacturer Print=WURTH, Max Operating Temperature=125°C, Min Operating Temperature=-40°C, Package=4-PC, Package Quantity=1, Supplier Part Number 1=9040408, Test Frequency=1kHz, TOLERANCE=30%, Voltage Rating=80V
L7: "CMC 6.8UH 2.1A 2LN 70 MOHM SMD", DC Resistance (DCR)=70mR, Inductance - Parallel=6.8uH, Inductance - Series=27.2uH, Manufacturer=COILCRAFT, Max DC Current=2.1A, Max Operating Temperature=85°C, Min Operating Temperature=-40°C, Package=N/A, Package Quantity=250, Supplier Part Number 1=994-MSD7342-682MLC, TOLERANCE=20%
L8: "FIXED IND 3.3UH 3.3A 27 MOHM SMD", Case/Package=Nonstandard, Current Rating=3.3A, DC Resistance (DCR)=27mR, Inductance=3.3μH, Manufacturer="TAIYO YUDEN", Max Operating Temperature=120°C, Min Operating Temperature=-25°C, Package=N/A, Resistor Type=Wirewound, Saturation Current=4A, Self Resonant Frequency=32MHz, Test Frequency=100kHz, TOLERANCE=30%
MH1 MH2 MH3 MH4: "HEX STANDOFF M4 ALUMINUM 51MM F-F", Manufacturer=MCMASTER-CARR, Manufacturer Part Number=95947A552, Package=N/A
Q1: "MOSFET P-CH 60V 8.6A PPAK SO-8", Continuous Drain Current=-8.6A, Drain To Source Resistance=0.0115Ω, Drain To Source Voltage=-60V, Gate To Source Voltage=20V, Manufacturer=VISHAY, Max Forward Diode Voltage=-1.2V, Max Junction Temp=+150°C, Package="PowerPAK SO-8", Power Dissipation=1.9W, Pulse Drain Current=-60A, Temperature="-55°C to +150°C", Temperature Range Low=-55°C, Typ Forward Diode Voltage=-0.8V
Q2: library part CMP-1048-00731-1, "TRANS NPN 45V 0.5A SOT23-3", Manufacturer=ONSEMI, Package=SOT-23-3
Q3: "1200V silicon carbide six-pack power module delivering maximum power density", Manufacturer=WOLFSPEED, Mfr_Name="Cree Wolfspeed", Package=FMC
Q4 Q5: library part CMP-1046-00010-1, "TRANS NPN 80V 8A DPAK", Manufacturer=ONSEMI, Package=TO-252-3
Q6 Q7: "MOSFET N-CH 120V 90A PWRDI5060-8", Manufacturer="DIODES INC", Package=8-PowerTDFN, Supplier Part Number 1=68AH9585
R1 R2 R3 R4 R5 R6 R7 R8 R9 R10 R11 R12: library part CMP-03211-002966-1, "RES 220K OHM 1% 2W 2512", Ambient Temperature Range High=+70°C, Manufacturer=TE, Package=2512, Power Rating=2W, Resistance=220kΩ, Temperature="-55°C to +155°C", Temperature Coefficient=±100ppm/°C, Temperature Range High=+155°C, Temperature Range Low=-55°C, TOLERANCE=0.01, Voltage Rating=500V
R13 R14 R15 R16 R17 R18 R19 R20 R21 R22 R23 R24 R25 R26 R27 R28 R29 R30 R31 R32 R33 R34 R35 R36 R122 R123 R124 R125 R126 R127 R128 R129 R130 R131 R132 R133 R134 R135 R136 R137 R138 R139 R140 R141 R142 R143 R144 R145: library part CMP-2003-04604-1, "RES 249K OHM 0.1% 1/4W 1206", Manufacturer="VISHAY DALE", Package=1206, POWER=0.25W, Resistance=249kΩ
R37 R39 R41 R43 R147 R149 R151 R153: "RES 4.99K OHM 1% 1/10W 0603", Case Code (Imperial)=0603, Case Code (Metric)=1608, Manufacturer=YAGEO, Max Operating Temperature=155°C, Max Power Dissipation=0.1W, Min Operating Temperature=-55°C, Package Quantity=1, Resistance=4.99kΩ, Resistance Tolerance=1%, Resistor Type="Thick Film", Supplier Part Number 1=1995595, Temperature Coefficient=100ppm/°C, Voltage Rating=75V, Voltage Rating (DC)=50V
R38 R152: "RES SMD 3.74K OHM 0.1% 1/5W 0603", Case Code (Imperial)=0603, Case Code (Metric)=1608, Manufacturer=PANASONIC, Max Operating Temperature=155°C, Max Power Dissipation=0.2W, Min Operating Temperature=-55°C, Resistance=3.74kΩ, Resistor Type="Thick Film", Temperature Coefficient=50ppm/°C, TOLERANCE=0.1%
R40 R42 R44 R146 R148 R150: "RES SMD 1.8K OHM 0.1% 1/5W 0603", Case Code (Imperial)=0603, Case Code (Metric)=1608, Manufacturer=PANASONIC, Max Operating Temperature=155°C, Max Power Dissipation=0.2W, Min Operating Temperature=-55°C, Resistance=1.8kΩ, Resistor Type="Thick Film", Temperature Coefficient=50ppm/°C, TOLERANCE=0.1%
R45 R46 R53 R54 R57 R62 R65 R68 R69 R70 R72 R76 R77 R78 R79 R80 R81 R91 R92 R94 R168 R171 R181 R182 R186 R194 R198 R199 R204: "RES SMD 49.9 OHM 1% 1/10W 0603", Case Code (Imperial)=0603, Case Code (Metric)=1608, Manufacturer=PANASONIC, Max Operating Temperature=155°C, Max Power Dissipation=100mW, Min Operating Temperature=-55°C, Package Quantity=5000, Power Rating=0.1W, Resistance=49.9Ω, Resistance Tolerance=1%, Resistor Type="Thick Film", Supplier Part Number 1=12AC1058, Temperature Coefficient=100ppm/°C, Voltage Rating=75V, Voltage Rating (DC)=50V, Working Voltage=6V
R47 R66 R73: "RES SMD 1.3K OHM 0.1% 1/10W 0603", Case Code (Imperial)=0603, Case Code (Metric)=1608, Manufacturer=PANASONIC, Manufacturer Part Number=ERA-3AEB132V, Max Operating Temperature=155°C, Max Power Dissipation=100mW, Min Operating Temperature=-55°C, Package Quantity=1, Power Rating=0.1W, Ratings=AEC-Q200, Resistance=1.3kΩ, Resistance Tolerance=0.1%, Resistor Type="Thin Film", Temperature Coefficient=25ppm/°C, Voltage Rating=75V
R48: "RES SMD 15.4K OHM 1% 1/10W 0603", Case Code (Imperial)=0603, Case Code (Metric)=1608, Manufacturer=SAMSUNG, Max Operating Temperature=155°C, Max Power Dissipation=100mW, Min Operating Temperature=-55°C, Package Quantity=1, Power Rating=0.1W, Resistance=15.4kΩ, Resistor Type="Thick Film", Temperature Coefficient=100ppm/°C, TOLERANCE=1%, Voltage Rating (DC)=50V
R49: "RES SMD 4.7K OHM 1% 1/10W 0603", Case Code (Imperial)=0603, Case Code (Metric)=1608, Manufacturer="VISHAY DALE", Max Operating Temperature=155°C, Max Power Dissipation=100mW, Min Operating Temperature=-55°C, Package Quantity=5000, Power Rating=0.1W, Resistance=4.7kΩ, Resistor Type="Thick Film", Supplier Part Number 1=541-3004-6-ND, Temperature Coefficient=100ppm/°C, TOLERANCE=1%, Voltage Rating=75V
R50 R52 R67 R71 R97 R102 R103 R105 R106 R113 R120 R157 R160 R163 R189 R206 R214 R218 R219 R222 R226 R228 R231 R232 R233 R234 R235 R236: "RES SMD 10K OHM 1% 1/10W 0603", Case Code (Imperial)=0603, Case Code (Metric)=1608, Manufacturer=PANASONIC, Manufacturer Part Number=ERJ-3EKF1002V, Max Operating Temperature=155°C, Max Power Dissipation=0.1W, Min Operating Temperature=-55°C, Package Quantity=1, Power Rating=100mW, Resistance=10kΩ, Resistance Tolerance=1%, Resistor Type="Thick Film", Supplier Part Number 1=1051156, Temperature Coefficient=100ppm/°C, Voltage Rating=75V
R51: "RES SMD 0 OHM JUMPER 1/10W 0603", Case Code (Imperial)=0603, Case Code (Metric)=1608, Manufacturer="VISHAY DALE", Manufacturer Part Number=CRCW06030000Z0EBC, Max Operating Temperature=155°C, Max Power Dissipation=100mW, Min Operating Temperature=-55°C, Package Quantity=10000, Power Rating=0.1W, Ratings=AEC-Q200, Resistance=0Ω, Resistor Type="Thick Film", Supplier Part Number 1=48P7902, Temperature Coefficient=100ppm/°C, TOLERANCE=1%, Voltage Rating=75V
R55 R56 R85 R87 R93: "RES SMD 2K OHM 0.5% 1/10W 0603", Case Code (Imperial)=0603, Case Code (Metric)=1608, Manufacturer=YAGEO, Max Operating Temperature=125°C, Max Power Dissipation=100mW, Min Operating Temperature=-55°C, Package Quantity=5000, Power Rating=0.1W, Resistance=2kΩ, Resistor Type="Thin Film", Supplier Part Number 1=6165116, Temperature Coefficient=50ppm/°C, TOLERANCE=0.5%, Voltage Rating=75V, Voltage Rating (DC)=50V
R58 R59 R193 R195 R196 R197: "RES SMD 0 OHM JUMPER 1/10W 0603", Case Code (Imperial)=0603, Case Code (Metric)=1608, Manufacturer="VISHAY DALE", Manufacturer Part Number=CRCW06030000Z0EBC, Max Operating Temperature=155°C, Max Power Dissipation=100mW, Min Operating Temperature=-55°C, Package Quantity=10000, Ratings=AEC-Q200, Resistance=0Ω, Resistor Type="Thick Film", Supplier Part Number 1=48P7902, Temperature Coefficient=100ppm/°C, TOLERANCE=1%, Voltage Rating=75V
R60 R63 R74 R82 R88 R89: library part CMP-2005-02198-1, "RES 0.91 OHM 1% 1W 1210", Manufacturer="VISHAY DALE", Package=1210, POWER=1W
R61 R64 R75 R83 R95 R96: "RES SMD 0 OHM JUMPER 3/4W 1210", Case Code (Imperial)=1210, Case Code (Metric)=3225, Manufacturer="VISHAY DALE", Max Operating Temperature=155°C, Max Power Dissipation=750mW, Min Operating Temperature=-55°C, Package Quantity=10, Power Rating=0.75W, Resistance=0Ω, Supplier Part Number 1=71-CRCW12100000Z0EAH
R84 R86 R90: library part CMP-1017-00397-1, "RES 100 OHM 1% 3/4W 2010", Case-Metric=5025, Manufacturer=YAGEO, Package=2010, POWER="0.75 W", TOLERANCE="1 %"
R98 R99 R112 R114 R117 R176 R177 R179 R180 R184 R187: "RES 100K OHM 1% 1/10W 0603", Case Code (Imperial)=0603, Case Code (Metric)=1608, Manufacturer=YAGEO, Max Operating Temperature=155°C, Max Power Dissipation=100mW, Min Operating Temperature=-55°C, Power Rating=0.1W, Resistance=100kΩ, Resistance Tolerance=1%, Resistor Type="Thick Film", Supplier Part Number 1=3697448, Temperature Coefficient=100ppm/°C, Voltage Rating=50V, Working Voltage=75V
R100: "RES SMD 165K OHM 1% 1/10W 0603", Case Code (Imperial)=0603, Case Code (Metric)=1608, Manufacturer=PANASONIC, Max Operating Temperature=155°C, Max Power Dissipation=100mW, Min Operating Temperature=-55°C, Package Quantity=1, Power Rating=0.1W, Resistance=165kΩ, Resistance Tolerance=1%, Resistor Type="Thick Film", Supplier Part Number 1=1058436, Temperature Coefficient=100ppm/°C, Voltage Rating=75V, Voltage Rating (DC)=50V
R101 R110: "RES 120K OHM 1% 1/10W 0603", Case Code (Imperial)=0603, Case Code (Metric)=1608, Manufacturer=YAGEO, Max Operating Temperature=155°C, Max Power Dissipation=0.1W, Min Operating Temperature=-55°C, Package Quantity=5000, Power Rating=100mW, Resistance=120kΩ, Resistance Tolerance=1%, Resistor Type="Thick Film", Supplier Part Number 1=5577309, Temperature Coefficient=100ppm/°C, Voltage Rating=50V, Working Voltage=75V
R104: "RES 20 OHM 5% 1/10W 0603", Case Code (Imperial)=0603, Case Code (Metric)=1608, Manufacturer=YAGEO, Max Operating Temperature=155°C, Max Power Dissipation=100mW, Min Operating Temperature=-55°C, Package Quantity=1, Power Rating=0.1W, Resistance=20Ω, Resistance Tolerance=5%, Resistor Type="Thick Film", Supplier Part Number 1=4144481, Temperature Coefficient=100ppm/°C, Voltage Rating=75V, Voltage Rating (DC)=50V
R107 R211: "RES 470K OHM 1% 1/10W 0603", Case Code (Imperial)=0603, Case Code (Metric)=1608, Manufacturer=YAGEO, Max Operating Temperature=155°C, Max Power Dissipation=100mW, Min Operating Temperature=-55°C, Package Quantity=1, Power Rating=0.1W, Resistance=470kΩ, Resistance Tolerance=1%, Resistor Type="Thick Film", Supplier Part Number 1=4599155, Temperature Coefficient=100ppm/°C, Voltage Rating=50V
R108 R119: "RES 56K OHM 1% 1/10W 0603", Case Code (Imperial)=0603, Case Code (Metric)=1608, Manufacturer=YAGEO, Max Operating Temperature=155°C, Max Power Dissipation=100mW, Min Operating Temperature=-55°C, Package Quantity=1, Power Rating=0.1W, Resistance=56kΩ, Resistance Tolerance=1%, Resistor Type="Thick Film", Supplier Part Number 1=7874498, Temperature Coefficient=100ppm/°C, Voltage Rating=75V, Voltage Rating (DC)=50V
R109 R121: "RES 45.3K OHM 1% 1/10W 0603", Case Code (Imperial)=0603, Case Code (Metric)=1608, Manufacturer=STACKPOLE, Max Operating Temperature=155°C, Max Power Dissipation=0.1W, Min Operating Temperature=-55°C, Resistance=45.3kΩ, Resistor Type="Thick Film", Temperature Coefficient=100ppm/°C, TOLERANCE=1%
R111: "RES SMD 200K OHM 1% 1/10W 0603", Case Code (Imperial)=0603, Case Code (Metric)=1608, Manufacturer=PANASONIC, Max Operating Temperature=155°C, Max Power Dissipation=0.1W, Min Operating Temperature=-55°C, Package Quantity=1, Power Rating=100mW, Resistance=200kΩ, Resistance Tolerance=1%, Resistor Type="Thick Film", Supplier Part Number 1=25AC9147, Temperature Coefficient=100ppm/°C, Voltage Rating=75V, Voltage Rating (DC)=50V
R115: library part CMP-2000-00337-2, "RES SMD 22K OHM 1% 1/10W 0603", Case Code (Imperial)=0603, Case Code (Metric)=1608, Manufacturer=PANASONIC, Max Operating Temperature="155 degC", Min Operating Temperature="-55 degC", Package Quantity=200, Power Rating=0.1W, Resistance=22kΩ, TOLERANCE=1%, Voltage Rating="50 V"
R116 R118: "RES 2.7M OHM 5% 1/10W 0603", Case Code (Imperial)=0603, Case Code (Metric)=1608, Manufacturer=YAGEO, Max Operating Temperature=155°C, Max Power Dissipation=100mW, Min Operating Temperature=-55°C, Package Quantity=1, Power Rating=0.1W, Resistance=2.7MΩ, Resistor Type="Thick Film", Temperature Coefficient=100ppm/°C, TOLERANCE=5%, Voltage Rating=75V, Voltage Rating (DC)=50V
R154 R166 R172: "RES 1.33K OHM 1% 1/10W 0603", Case Code (Imperial)=0603, Case Code (Metric)=1608, Manufacturer=STACKPOLE, Max Operating Temperature=155°C, Max Power Dissipation=100mW, Min Operating Temperature=-55°C, Power Rating=0.1W, Resistance=1.33kΩ, Resistor Type="Thick Film", Temperature Coefficient=100ppm/°C, TOLERANCE=1%
R155 R167 R173: "RES 7.15K OHM 1% 1/10W 0603", Case Code (Imperial)=0603, Case Code (Metric)=1608, Manufacturer=STACKPOLE, Max Operating Temperature=155°C, Max Power Dissipation=100mW, Min Operating Temperature=-55°C, Power Rating=0.1W, Resistance=7.15kΩ, Resistor Type="Thick Film", Temperature Coefficient=100ppm/°C, TOLERANCE=1%
R156: "RES SMD 120 OHM 5% 1/10W 0603", Case Code (Imperial)=0603, Case Code (Metric)=1608, Manufacturer=YAGEO, Max Operating Temperature=155°C, Max Power Dissipation=0.1W, Min Operating Temperature=-55°C, Package Quantity=1, Power Rating=100mW, Resistance=120Ω, Resistance Tolerance=5%, Resistor Type="Thick Film", Supplier Part Number 1=2424206, Temperature Coefficient=100ppm/°C, Voltage Rating=50V
R158: "RES SMD 97.6K OHM 1% 1/10W 0603", Case Code (Imperial)=0603, Case Code (Metric)=1608, Manufacturer=PANASONIC, Max Operating Temperature=155°C, Max Power Dissipation=0.1W, Min Operating Temperature=-55°C, Package Quantity=1, Power Rating=100mW, Resistance=97.6kΩ, Resistance Tolerance=1%, Resistor Type="Thick Film", Supplier Part Number 1=27AC5274, Temperature Coefficient=100ppm/°C, Voltage Rating=75V, Voltage Rating (DC)=50V
R159: "RES 249K OHM 1% 1/10W 0603", Case Code (Imperial)=0603, Case Code (Metric)=1608, Manufacturer=STACKPOLE, Max Operating Temperature=155°C, Max Power Dissipation=0.1W, Min Operating Temperature=-55°C, Resistance=249kΩ, Resistor Type="Thick Film", Temperature Coefficient=100ppm/°C, TOLERANCE=1%
R161: "RES 330 OHM 1% 1/10W 0603", Case Code (Imperial)=0603, Case Code (Metric)=1608, Manufacturer=YAGEO, Max Operating Temperature=155°C, Min Operating Temperature=-55°C, Power Rating=0.1W, Resistance=330Ω, Resistor Type="Thick Film", Supplier Part Number 1=4067719, Temperature Coefficient=100ppm/°C, TOLERANCE=1%, Voltage Rating=50V
R162: "RES SMD 20K OHM 1% 1/10W 0603", Case Code (Imperial)=0603, Case Code (Metric)=1608, Manufacturer="VISHAY DALE", Max Operating Temperature=155°C, Max Power Dissipation=100mW, Min Operating Temperature=-55°C, Package Quantity=5000, Power Rating=0.1W, Resistance=20kΩ, Resistance Tolerance=1%, Resistor Type="Thick Film", Temperature Coefficient=100ppm/°C, Voltage Rating=75V
R164 R169 R174: "RES SMD 4.02KOHM 0.1% 1/10W 0603", Case Code (Imperial)=0603, Case Code (Metric)=1608, Manufacturer=PANASONIC, Manufacturer Part Number=ERA-3AEB4021V, Max Operating Temperature=155°C, Max Power Dissipation=100mW, Min Operating Temperature=-55°C, Package Quantity=1, Power Rating=0.1W, Resistance=4.02kΩ, Resistance Tolerance=0.1%, Resistor Type="Thin Film", Supplier Part Number 1=7087616, Temperature Coefficient=25ppm/°C, Voltage Rating=75V
R165 R170 R175: "RES 7.87K OHM 1% 1/10W 0603", Case Code (Imperial)=0603, Case Code (Metric)=1608, Manufacturer=YAGEO, Max Operating Temperature=155°C, Max Power Dissipation=0.1W, Min Operating Temperature=-55°C, Package Quantity=1, Power Rating=100mW, Resistance=7.87kΩ, Resistor Type="Thick Film", Supplier Part Number 1=49AK2736, Temperature Coefficient=100ppm/°C, TOLERANCE=1%, Voltage Rating=50V
R178 R183 R185 R188 R200 R201 R202 R203: "RES SMD 1K OHM 5% 1/8W 0805", Case Code (Imperial)=0805, Case Code (Metric)=2012, Manufacturer="VISHAY DALE", Max Operating Temperature=155°C, Max Power Dissipation=125mW, Min Operating Temperature=-55°C, Package Quantity=5000, Power Rating=0.13W, Resistance=1kΩ, Resistor Type="Thick Film", Temperature Coefficient=200ppm/°C, TOLERANCE=5%, Voltage Rating=150V
R190 R191 R192: "RES 680 OHM 1% 1/10W 0603", Case Code (Imperial)=0603, Case Code (Metric)=1608, Manufacturer=YAGEO, Max Operating Temperature=155°C, Max Power Dissipation=100mW, Min Operating Temperature=-55°C, Package Quantity=1, Power Rating=0.1W, Resistance=680Ω, Resistance Tolerance=1%, Resistor Type="Thick Film", Supplier Part Number 1=6789788, Temperature Coefficient=100ppm/°C, Voltage Rating=50V
R205 R207 R208: "RES 249 OHM 1% 1/4W 1206", Case Code (Imperial)=1206, Case Code (Metric)=3216, Manufacturer=YAGEO, Max Operating Temperature=155°C, Max Power Dissipation=250mW, Min Operating Temperature=-55°C, Power Rating=0.25W, Resistance=249Ω, Resistor Type="Thick Film", Supplier Part Number 1=1142064, Temperature Coefficient=100ppm/°C, TOLERANCE=1%, Voltage Rating=200V
R209 R215: "RES SMD 3.9K OHM 1% 1/10W 0603", Case Code (Imperial)=0603, Case Code (Metric)=1608, Manufacturer=PANASONIC, Manufacturer Part Number=ERJ-3EKF3901V, Max Operating Temperature=155°C, Max Power Dissipation=100mW, Min Operating Temperature=-55°C, Package Quantity=1, Power Rating=0.1W, Resistance=3.9kΩ, Resistance Tolerance=1%, Resistor Type="Thick Film", Supplier Part Number 1=1229307, Temperature Coefficient=100ppm/°C, Voltage Rating=75V
R210: "RES 499 OHM 1% 1/8W 0805", Case Code (Imperial)=0805, Case Code (Metric)=2012, Manufacturer=YAGEO, Max Operating Temperature=155°C, Max Power Dissipation=0.13W, Min Operating Temperature=-55°C, Package Quantity=1, Power Rating=125mW, Resistance=499Ω, Resistor Type="Thick Film", Supplier Part Number 1=5825161, Temperature Coefficient=100ppm/°C, TOLERANCE=1%, Voltage Rating=150V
